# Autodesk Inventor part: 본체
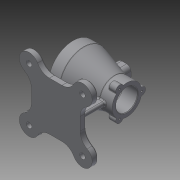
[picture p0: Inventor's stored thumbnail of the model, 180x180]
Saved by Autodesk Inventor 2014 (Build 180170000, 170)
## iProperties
Created: 2018-03
Part Number: 본체
Material: Generic
Document SubType Name: Modeling
Designer: kb542
Density: 1 g/cm^3
Appearance: Default
Author: kb542
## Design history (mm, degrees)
sketch "스케치1"
  geometry: L1 (-50, 0)-(50, 0); L2 (-50, 0)-(-50, 45); L3 (-50, 45)-(-30, 45); L4 (50, 27.5)-(50, 0); L5 (-30, 45)-(27, 27.5); L6 (27, 27.5)-(50, 27.5); 2 further points
  constraints: 12 end point, 2 perpendicular, 1 coincident, 1 horizontal, 1 midpoint, 1 parallel
  dimensions: "d0" = 100 distance of L1.start L1.end; "d1" = 20 distance from line of L3.end L2; "d2" = 90 diameter of L3 L1; "d3" = 55 diameter of L6 L1; "d4" = 23 distance from line of L5.end L4
revolve "회전1" sketch "스케치1" stored, may be unused: angle "d5" = 90 deg
sketch "스케치2"
  geometry: L1 (-50, -45)-(-50, 45) reference; L2 (-30, -45)-(-30, 45) reference; L3 (27, -27.5)-(27, 27.5) reference; L4 (50, -27.5)-(50, 27.5) reference; L5 (-50, 0)-(50, 0) reference; L6 (-50, 0)-(-50, 35); L7 (-50, 35)-(-27, 35); L8 (-27, 35)-(-27, 26); L9 (-27, 26)-(20, 26); L10 (20, 26)-(20, 20); L11 (20, 20)-(50, 20); 3 further points
  constraints: 12 end point, 3 perpendicular, 2 parallel, 2 point on line
  dimensions: "d6" = 40 diameter of L11 L5; "d7" = 70 diameter of L7 L5; "d8" = 23 distance between parallel lines of L1 L8; "d9" = 30 distance from line of L11.end L10; "d10" = 47 distance between parallel lines of L10 L8 (derived); "d11" = 52 diameter of L9 L5
revolve "회전2" sketch "스케치2" stored, may be unused: angle "d12" = 90 deg
sketch "스케치3" dims "d13" = 55
  geometry: L1 (0, 0)-(0, 45.507); C1 r 27.5 at (0, 0) reference; C2 r 7 at (0, 27.5)
  constraints: 2 end point, 1 centre point, 1 coincident, 1 point on line, 1 vertical, 1 vertical alignment, 2 other
  dimensions: "d14" = 14 diameter of C2
extrude "돌출1" join sketch "스케치3" distance "d15" = 15; taper "d16" = 0 deg
hole "구멍1" diameter "d22" = 3.242; stored, may be unused: countersink angle "d26" = 90 deg, drill point angle "d28" = 118 deg; dims "d20" = 10, "d21" = 10, "d23" = 9, "d24" = 4, "d25" = 2, "d27" = 11
fillet "모깎기1" dims "d29" = 3
fillet "모깎기2" dims "d30" = 1
sketch "스케치4" dims "d31" = 80
  geometry: C1 r 35 at (0, 0) reference; C2 r 45 at (0, 0) reference; 2 further points
  constraints: 2 vertical alignment, 1 coincident, 2 other
hole "구멍2" sketch "스케치4" at (0, 40) diameter "d32" = 3.242; stored, may be unused: countersink angle "d36" = 90 deg, drill point angle "d38" = 118 deg; dims "d33" = 9, "d34" = 4, "d35" = 2, "d37" = 11
node "작업 평면1"
sketch "스케치5"
  geometry: L1 (-90, -7)-(-90, 7) reference; L2 (10, 45)-(10, -45) reference; L3 (-52.5, 12.5)-(-27.5, 12.5); L4 (-27.5, 12.5)-(-27.5, -12.5); L5 (-27.5, -12.5)-(-52.5, -12.5); L6 (-52.5, -12.5)-(-52.5, 12.5); L7 (-47.5, 7.5)-(-32.5, 7.5); L8 (-32.5, 7.5)-(-32.5, -7.5); L9 (-32.5, -7.5)-(-47.5, -7.5); L10 (-47.5, -7.5)-(-47.5, 7.5); 8 further points
  constraints: 16 end point, 5 midpoint, 4 parallel, 3 horizontal alignment, 2 horizontal, 2 perpendicular, 2 vertical alignment
  dimensions: "d42" = 25 distance of L3.start L3.end; "d43" = 25 distance between parallel lines of L3 L5; "d46" = 15 distance of L7.start L7.end; "d47" = 15 distance between parallel lines of L9 L7
extrude "돌출2" join sketch "스케치5" stored distance "d48" = 15; taper "d49" = 0 deg
extrude "돌출3" cut sketch "스케치5" stored distance "d50" = 15; taper "d51" = 0 deg
fillet "모깎기3" dims "d52" = 8
fillet "모깎기4" dims "d53" = 3
fillet "모깎기5" dims "d54" = 1
node "작업 평면2"
sketch "스케치6"
  geometry: L1 (-50, 27.5)-(-50, 7.718) reference; L2 (50, 45)-(50, -45) reference; L3 (50, 45)-(50, -45) reference; L4 (30, 45)-(30, -45) reference; L5 (50, -45)-(30, -45) reference; L6 (-50, -7.718)-(-50, -27.5) reference; L7 (-50, -7)-(-50, 7) reference; L8 (-45, 45)-(45, 45); L9 (45, 45)-(45, -45); L10 (45, -45)-(-45, -45); L11 (-45, -45)-(-45, 45); L12 (0, 0)-(-49.497, 49.497); L13 (0, 0)-(-70, 0); L14 (0, 0)-(0, 45); L15 (0, 0)-(45, -45); L16 (-45, -45)-(45, 45); L17 (45, 0)-(0, 0); A1 r 70 centre (0, 0) between (-70, 0) and (-49.497, 49.497); A2 r 18 centre (-49.497, 49.497) between (-58.08, 33.675) and (-33.675, 58.08); A3 r 25 centre (-70, 11.7) between (-45, 11.7) and (-58.08, 33.675); A4 r 25 centre (-70, -11.7) between (-58.08, -33.675) and (-45, -11.7); A5 r 18 centre (49.497, -49.497) between (58.08, -33.675) and (33.675, -58.08); A6 r 25 centre (70, 11.7) between (58.08, 33.675) and (45, 11.7); A7 r 25 centre (70, -11.7) between (45, -11.7) and (58.08, -33.675); A8 r 25 centre (-11.7, -70) between (-11.7, -45) and (-34.898, -60.681); A9 r 25 centre (11.7, -70) between (33.675, -58.08) and (11.7, -45); A10 r 25 centre (-11.7, 70) between (-33.675, 58.08) and (-11.7, 45); A11 r 25 centre (11.7, 70) between (11.7, 45) and (33.675, 58.08); 13 further points
  constraints: 25 point on circle, 21 end point, 19 symmetric about line, 11 centre point, 5 perpendicular, 4 point on line, 4 tangent, 3 midpoint, 2 coincident, 2 parallel, 1 horizontal, 1 horizontal alignment, 1 vertical alignment, 16 other
  dimensions: "d56" = 90 distance between parallel lines of L10 L8; "d57" = 90 distance between parallel lines of L11 L9; "d58" = 140 diameter of A1; "d59" = 45 deg angle of L13 L12; "d60" = 36 diameter of A2; "d63" = 25 radius of A4; "d64" = 25 radius of A3; "d67" = 25 radius of A8
extrude "돌출4" join sketch "스케치6" distance "d68" = 12; taper "d69" = 0 deg
fillet "모깎기6" dims "d70" = 25
fillet "모깎기7" dims "d71" = 25
sketch "스케치7"
  geometry: A1 r 18 centre (49.497, 49.497) between (58.08, 33.675) and (33.675, 58.08) reference; A2 r 18 centre (-49.497, 49.497) between (-33.675, 58.08) and (-58.08, 33.675) reference; A3 r 18 centre (-49.497, -49.497) between (-58.08, -33.675) and (-33.675, -58.08) reference; A4 r 18 centre (49.497, -49.497) between (33.675, -58.08) and (58.08, -33.675) reference; 5 further points
  constraints: 4 coincident
hole "구멍3" sketch "스케치7" at (-49.497, 49.497), (49.497, 49.497), (49.497, -49.497), (-49.497, -49.497) diameter "d73" = 10; stored, may be unused: countersink angle "d77" = 90 deg, drill point angle "d79" = 118 deg; dims "d74" = 9, "d75" = 4, "d76" = 2, "d78" = 11
chamfer "모따기1" distance "d80" = 3; stored, may be unused: second distance "d81" = 2, angle "d82" = 45 deg
chamfer "모따기2" distance "d83" = 1; stored, may be unused: second distance "d84" = 2, angle "d85" = 45 deg
fillet "모깎기8" dims "d86" = 3
chamfer "모따기3" distance "d87" = 1; stored, may be unused: second distance "d88" = 2, angle "d89" = 45 deg
node "작업 평면3"
sketch "스케치8"
  geometry: L1 (-70, -11.7)-(-70, 11.7) reference; L2 (-70, 11.7)-(-70, 36.312) reference; L3 (-70, -36.312)-(-70, -11.7) reference; L4 (-70, 64.497)-(-70, 36.312) reference; L5 (-70, -36.312)-(-70, -64.497) reference; L6 (-70, 24)-(-28.464, 20.366); L7 (-70, -24)-(-28.464, -20.366); L8 (-70, 24)-(-70, -24); A1 r 35 centre (0, 0) between (-28.464, 20.366) and (-28.464, -20.366) reference; A2 r 35 centre (0, 0) between (-28.464, 20.366) and (-28.464, -20.366); 3 further points
  constraints: 6 end point, 4 point on circle, 2 point on line, 1 centre point, 1 coincident, 1 collinear, 1 equal length
  dimensions: "d91" = 24 vertical distance of point (0, 0) L6.start; "d92" = 95 deg angle of L6 L2; "d93" = 95 deg angle of L5 L7
extrude "돌출5" join sketch "스케치8" stored distance "d94" = 8; taper "d95" = 0 deg
node "작업 평면4"
sketch "스케치9"
  geometry: L1 (-50, -45)-(-30, -45) reference; L2 (-30, -45)-(27, -27.5) reference; L3 (50, -6.513)-(38, -6.513) reference; L4 (50, 26.395)-(50, -6.513) reference; L5 (38, 26.395)-(50, 26.395) reference; L6 (34, 27.237)-(34, 27.237) reference; L7 (50, 26.395)-(38, 26.395) reference; L8 (50, -6.513)-(50, 26.395) reference; L9 (38, -6.513)-(50, -6.513) reference; L10 (34, -16.905)-(34, -10.332) reference; L11 (50, -19.881)-(38, -19.881) reference; L12 (50, -19.881)-(50, -19.881) reference; L13 (38, -19.881)-(50, -19.881) reference; L14 (34, -10.332)-(34, -16.905) reference; L15 (27, -27.5)-(27, 27.5) reference; L16 (4, -28.464)-(4, -70) reference; L17 (-4, -70)-(-4, -30.777) reference; L18 (-11.7, -70)-(-36.312, -70) reference; L19 (-64.497, -70)-(-36.312, -70) reference; L20 (36.312, -70)-(11.7, -70) reference; L21 (36.312, -70)-(64.497, -70) reference; L22 (11.7, -70)-(-11.7, -70) reference; L23 (27, -27.5)-(50, -27.5) reference; L24 (-37, -45)-(-37, -70); L25 (37, -70)-(37, -27.5); 3 further points
  constraints: 4 end point, 4 point on line, 1 perpendicular, 1 vertical, 6 other
  dimensions: "d97" = 37 distance from line of L24 point (0, 0); "d98" = 37 distance from line of point (0, 0) L25
feature "리브1" sketch "스케치9" dims "d99" = 1, "d100" = 8, "d101" = 0, "d102" = 0, "d103" = 1, "d104" = 1
fillet "모깎기9" dims "d105" = 3
fillet "모깎기10" dims "d106" = 3
fillet "모깎기11" dims "d107" = 3
sketch "스케치11"
  geometry: L1 (45, -11.7)-(45, 11.7) reference; 2 further points
  constraints: 1 other
  dimensions: "d108" = 45 distance from line of L1 point (0, -35); "d109" = 35 distance of point (0, -35) point (0, 0)
feature "엠보싱1" sketch "스케치11" dims "d0" = 100, "d1" = 20, "d2" = 90, "d3" = 55, "d4" = 23, "d110" = 0.5, "d111" = 0
node "솔리드1"
pattern_circular "원형 패턴1" dims "d18" = 360 deg
pattern_circular "원형 패턴2" dims angle "d40" = 360 deg
mirror "대칭1"
node "투영된 루프1"
node "투영된 루프2"
node "투영된 루프3"
node "투영된 루프4"
other parameters: "d55" = -82, "d90" = 0, "d96" = 0
